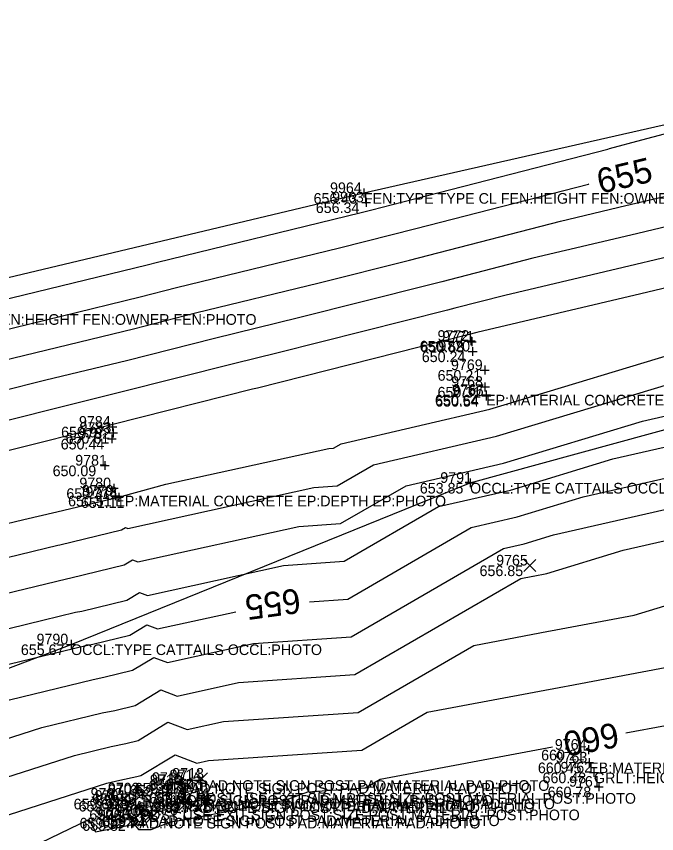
# Model space of a CAD drawing. Extents: x 2129350 to 2137777, y 657588 to 659885.
# Drawn here: x 2134017.7 to 2134089.9, y 659044.8 to 659137 of the extents above; entities that cross this region are included whole.
import ezdxf

# ---------------------------------------------------------------- set-up
doc = ezdxf.new("R2010")
doc.units = 0
for name, color, linetype in [('DT_X_Contour_Major', 7, 'Continuous'), ('DT_X_Contour_Minor', 7, 'Continuous'), ('DT_X_TIN_Hull', 7, 'Continuous'), ('RD_X_Cells', 7, 'Continuous'), ('SV_X_Occupation_Line', 7, 'Continuous'), ('SV_X_Random_Point', 7, 'Continuous'), ('SV_X_Shot_Marker', 7, 'Continuous'), ('SV_X_Text_Comment', 7, 'Continuous'), ('SV_X_Text_Elevation', 7, 'Continuous'), ('SV_X_Text_Name', 7, 'Continuous')]:
    doc.layers.add(name, color=color, linetype=linetype)

msp = doc.modelspace()

# ---------------------------------------------------------------- linework, layer by layer
at = {"layer": 'DT_X_Contour_Major'}
for points in [[(2133984.763, 659096.562), (2133998.002, 659097.665), (2134001.64, 659097.968), (2134007.291, 659099.346), (2134013.833, 659100.986), (2134031.695, 659105.339), (2134035.772, 659106.371), (2134054.144, 659110.846), (2134059.912, 659112.305), (2134062.733, 659113.033), (2134082.191, 659118.049), (2134082.236, 659118.06)], [(2134050.751, 659070.954), (2134055.065, 659071.25), (2134068.969, 659079.308), (2134074.177, 659080.515), (2134081.606, 659082.765), (2134111.977, 659089.686), (2134119.808, 659092.155), (2134130.097, 659094.792), (2134146.022, 659099.168)], [(2134086.41, 659056.154), (2134099.797, 659058.669), (2134106.214, 659059.949), (2134110.948, 659060.932), (2134128.703, 659064.536), (2134130.835, 659065.039), (2134151.277, 659070.077), (2134152.823, 659070.441), (2134154.17, 659070.79), (2134176.696, 659076.829), (2134178.859, 659076.97), (2134180.373, 659077.349), (2134180.728, 659077.11), (2134183.835, 659077.795)], [(2133949.597, 659046.76), (2133964.098, 659048.355), (2133973.018, 659050.173), (2133975.83, 659047.42), (2133976.393, 659049.146), (2133976.617, 659049.192), (2133986.103, 659056.365), (2133987.605, 659056.69), (2133997.253, 659058.741), (2133998.731, 659059.107), (2134000.25, 659059.52), (2134001.796, 659059.974), (2134002.899, 659059.699), (2134013.292, 659063.037), (2134025.401, 659065.979), (2134026.335, 659066.172), (2134030.508, 659067.186), (2134032.419, 659068.346), (2134033.637, 659067.879), (2134042.451, 659069.822)], [(2133982.762, 659033.609), (2133982.831, 659033.821), (2133983.338, 659033.924), (2133984.503, 659034.806), (2133984.688, 659034.846), (2134007.46, 659039.688), (2134007.609, 659039.725), (2134007.762, 659039.766), (2134007.917, 659039.812), (2134008.028, 659039.784), (2134020.538, 659043.802), (2134025.906, 659046.408), (2134026.667, 659044.999), (2134031.019, 659045.857), (2134031.487, 659045.273), (2134032.919, 659045.275), (2134035.135, 659046.152), (2134036.568, 659046.362), (2134048.024, 659048.581), (2134050.58, 659049.52), (2134057.054, 659049.964), (2134058.731, 659050.936), (2134078.155, 659054.6)]]:
    msp.add_lwpolyline(points, dxfattribs=at)
at = {"layer": 'DT_X_Contour_Minor'}
for points in [[(2133976.674, 659092.847), (2133977.522, 659091.483), (2133980.569, 659092.251), (2133984.24, 659093.177), (2133999.557, 659094.453), (2134002.293, 659094.681), (2134006.542, 659095.717), (2134017.451, 659098.452), (2134030.921, 659101.735), (2134037.914, 659103.505), (2134051.837, 659106.896), (2134062.046, 659109.479), (2134064.2, 659110.034), (2134079.051, 659113.863), (2134086.408, 659115.608), (2134096.359, 659117.968), (2134110.672, 659121.688), (2134113.284, 659122.316), (2134123.738, 659124.847), (2134133.178, 659127.116), (2134143.637, 659129.649), (2134152.762, 659131.842), (2134168.026, 659135.54)], [(2134167.919, 659131.932), (2134158.207, 659129.579), (2134143.576, 659126.064), (2134136.854, 659124.435), (2134122.145, 659120.901), (2134115.361, 659119.258), (2134111.231, 659118.265), (2134101.918, 659115.845), (2134086.965, 659112.298), (2134075.91, 659109.676), (2134065.666, 659107.035), (2134064.18, 659106.652), (2134049.53, 659102.946), (2134040.056, 659100.638), (2134030.148, 659098.13), (2134021.07, 659095.918), (2134005.794, 659092.088), (2134002.946, 659091.394), (2134001.112, 659091.241), (2133990.847, 659090.386), (2133980.378, 659087.745), (2133978.347, 659087.233), (2133975.261, 659092.198)], [(2133993.65, 659100.644), (2133996.447, 659100.877), (2134000.987, 659101.255), (2134008.04, 659102.975), (2134010.215, 659103.52), (2134032.469, 659108.943), (2134033.63, 659109.237), (2134056.451, 659114.796), (2134057.778, 659115.132), (2134061.267, 659116.032), (2134084.359, 659121.985), (2134084.561, 659122.058), (2134088.214, 659123.011), (2134109.184, 659128.595), (2134118.743, 659130.987)], [(2134163.653, 659127.317), (2134143.515, 659122.478), (2134140.529, 659121.755), (2134120.552, 659116.954), (2134117.438, 659116.2), (2134111.791, 659114.843), (2134107.476, 659113.722), (2134087.522, 659108.989), (2134072.77, 659105.489), (2134067.132, 659104.036), (2134066.314, 659103.825), (2134047.223, 659098.996), (2134042.198, 659097.772), (2134029.374, 659094.526), (2134024.688, 659093.384), (2134005.045, 659088.459), (2134003.599, 659088.107), (2134002.668, 659088.029), (2133997.455, 659087.595), (2133980.186, 659083.24), (2133979.173, 659082.984), (2133973.849, 659091.549)], [(2134095.816, 659107.514), (2134088.079, 659105.679), (2134069.63, 659101.303), (2134068.598, 659101.037), (2134068.448, 659100.998), (2134044.916, 659095.046), (2134044.34, 659094.906), (2134028.6, 659090.922), (2134028.306, 659090.85), (2134004.296, 659084.83), (2134004.251, 659084.82), (2134004.223, 659084.817), (2134004.063, 659084.804), (2133982.451, 659079.354), (2133980.16, 659078.782), (2133979.923, 659078.72), (2133973.446, 659077.098), (2133973.417, 659077.074), (2133973.133, 659079.326), (2133972.456, 659091.406)], [(2133999.642, 659075.668), (2134018.561, 659080.227), (2134022.304, 659081.087), (2134029.227, 659082.753), (2134031.57, 659083.394), (2134034.59, 659084.198), (2134052.934, 659088.241), (2134053.474, 659088.278), (2134054.316, 659088.767), (2134071.063, 659092.646), (2134094.947, 659099.882)], [(2134002.314, 659072.449), (2134022.394, 659077.328), (2134022.616, 659077.373), (2134029.566, 659079.062), (2134030.017, 659079.336), (2134030.304, 659079.226), (2134051.239, 659083.841), (2134053.872, 659084.021), (2134057.98, 659086.402), (2134071.841, 659089.613), (2134091.612, 659095.603)], [(2134005.973, 659069.312), (2134023.397, 659073.545), (2134023.855, 659073.64), (2134029.88, 659075.103), (2134030.817, 659075.672), (2134031.415, 659075.443), (2134049.545, 659079.44), (2134054.269, 659079.764), (2134061.643, 659084.037), (2134072.62, 659086.58), (2134088.277, 659091.324), (2134103.511, 659094.795)], [(2134009.632, 659066.175), (2134024.399, 659069.762), (2134025.095, 659069.906), (2134030.194, 659071.144), (2134031.618, 659072.009), (2134032.526, 659071.661), (2134047.85, 659075.039), (2134054.667, 659075.507), (2134065.306, 659081.673), (2134073.399, 659083.547), (2134084.941, 659087.045), (2134107.744, 659092.241)], [(2133985.855, 659043.583), (2134003.377, 659047.309), (2134004.058, 659047.477), (2134004.757, 659047.668), (2134005.469, 659047.877), (2134005.976, 659047.75), (2134024.269, 659053.625), (2134028.407, 659054.63), (2134030.054, 659054.97), (2134031.451, 659055.309), (2134034.821, 659057.356), (2134036.97, 659056.532), (2134041.073, 659057.437), (2134056.258, 659058.478), (2134069.282, 659066.027), (2134077.71, 659067.617), (2134077.927, 659067.658), (2134087.349, 659069.428), (2134121.013, 659079.703), (2134124.053, 659080.211), (2134127.308, 659081.14), (2134164.102, 659088.042)], [(2133963.234, 659044.551), (2133974.897, 659046.928), (2133977.216, 659044.658), (2133977.681, 659046.081), (2133977.961, 659046.138), (2133985.783, 659052.053), (2133987.022, 659052.321), (2133999.295, 659054.931), (2134000.507, 659055.23), (2134001.752, 659055.57), (2134003.02, 659055.942), (2134003.924, 659055.716), (2134016.951, 659059.9), (2134026.403, 659062.196), (2134027.575, 659062.438), (2134030.823, 659063.227), (2134033.22, 659064.682), (2134034.748, 659064.097), (2134044.461, 659066.238), (2134055.463, 659066.993), (2134072.632, 659076.944), (2134074.956, 659077.482), (2134078.271, 659078.486), (2134116.21, 659087.131)], [(2133979.305, 659043.085), (2133985.463, 659047.741), (2133986.439, 659047.952), (2134001.336, 659051.12), (2134002.282, 659051.354), (2134003.255, 659051.619), (2134004.244, 659051.909), (2134004.95, 659051.733), (2134020.61, 659056.762), (2134027.405, 659058.413), (2134028.814, 659058.704), (2134031.137, 659059.268), (2134034.021, 659061.019), (2134035.859, 659060.314), (2134042.767, 659061.837), (2134055.861, 659062.736), (2134074.558, 659073.572), (2134075.929, 659073.831), (2134075.965, 659073.838), (2134077.498, 659074.126), (2134086.096, 659076.75), (2134120.442, 659084.577)], [(2134007.002, 659043.767), (2134027.928, 659050.488), (2134029.41, 659050.848), (2134031.294, 659051.236), (2134031.765, 659051.351), (2134035.622, 659053.692), (2134038.081, 659052.75), (2134039.378, 659053.036), (2134056.656, 659054.221), (2134064.007, 659058.482), (2134079.49, 659061.402), (2134079.89, 659061.478), (2134097.201, 659064.73), (2134113.485, 659069.7), (2134126.289, 659071.838), (2134139.998, 659075.753), (2134158.234, 659079.174), (2134175.353, 659083.764)]]:
    msp.add_lwpolyline(points, dxfattribs=at)
at = {"layer": 'DT_X_TIN_Hull'}
msp.add_lwpolyline([(2134356.026, 659185.946), (2134303.515, 659173.01), (2134259.229, 659162.306), (2134216.068, 659153.312), (2134168.251, 659141.961), (2134125.876, 659132.549), (2134109.045, 659128.864), (2134056.892, 659117.026), (2133999.593, 659103.374), (2133973.207, 659091.255), (2133972.954, 659091.387), (2133971.1, 659091.461), (2133969.763, 659091.144), (2133967.604, 659091.082), (2133965.702, 659091.19), (2133965.451, 659091.228), (2133933.981, 659084.789), (2133923.278, 659083.026), (2133873.948, 659069.271), (2133819.308, 659054.807), (2133767.477, 659040.462), (2133725.976, 659030.566)], dxfattribs=at)
at = {"layer": 'RD_X_Cells'}
for points in [[(2134036.906, 659048.32), (2134038.353, 659047.927), (2134039.416, 659048.984), (2134039.032, 659050.434), (2134037.585, 659050.827), (2134036.522, 659049.77), (2134036.906, 659048.32)], [(2134030.571, 659046.464), (2134032.018, 659046.071), (2134033.081, 659047.128), (2134032.697, 659048.578), (2134031.25, 659048.971), (2134030.187, 659047.914), (2134030.571, 659046.464)]]:
    msp.add_lwpolyline(points, dxfattribs=at)
at = {"layer": 'SV_X_Occupation_Line'}
msp.add_lwpolyline([(2133964.235, 659050.817), (2133988.958, 659052.851), (2134023.903, 659066.142), (2134068.855, 659084.352), (2134158.11, 659108.791), (2134245.538, 659131.154), (2134308.77, 659149.808)], dxfattribs=at)
at = {"layer": 'SV_X_Random_Point'}
for p, q in [((2134074.918, 659074.372), (2134076.252, 659075.706)), ((2134074.918, 659075.706), (2134076.252, 659074.372)), ((2134037.929, 659050.333), (2134039.263, 659051.669)), ((2134037.929, 659051.669), (2134039.263, 659050.333)), ((2134035.49, 659049.61), (2134036.824, 659050.944)), ((2134035.49, 659050.944), (2134036.824, 659049.61)), ((2134031.26, 659048.666), (2134032.594, 659050.002)), ((2134031.26, 659050.002), (2134032.594, 659048.666)), ((2134029.303, 659048.071), (2134030.637, 659049.406)), ((2134029.303, 659049.406), (2134030.637, 659048.071)), ((2134036.06, 659047.411), (2134037.394, 659048.747)), ((2134036.06, 659048.747), (2134037.394, 659047.411)), ((2134038.491, 659047.792), (2134039.825, 659049.127)), ((2134038.491, 659049.127), (2134039.825, 659047.792)), ((2134030.147, 659045.654), (2134031.481, 659046.988)), ((2134030.147, 659046.988), (2134031.481, 659045.654)), ((2134032.36, 659046.02), (2134033.694, 659047.355)), ((2134032.36, 659047.355), (2134033.694, 659046.02))]:
    msp.add_line(p, q, dxfattribs=at)
at = {"layer": 'SV_X_Shot_Marker'}
for p, q in [((2134056.394, 659117.026), (2134057.394, 659117.026)), ((2134056.894, 659117.526), (2134056.894, 659116.526)), ((2134056.894, 659117.026), (2134056.894, 659117.026)), ((2134057.142, 659116.477), (2134057.142, 659115.477)), ((2134056.642, 659115.977), (2134057.642, 659115.977)), ((2134057.142, 659115.977), (2134057.142, 659115.977)), ((2134068.428, 659100.366), (2134069.428, 659100.366)), ((2134068.928, 659100.866), (2134068.928, 659099.866)), ((2134068.928, 659100.366), (2134068.928, 659100.366)), ((2134069.04, 659100.764), (2134069.04, 659099.764)), ((2134068.54, 659100.264), (2134069.54, 659100.264)), ((2134069.04, 659100.264), (2134069.04, 659100.264)), ((2134069.14, 659099.669), (2134069.14, 659098.669)), ((2134068.64, 659099.169), (2134069.64, 659099.169)), ((2134069.14, 659099.169), (2134069.14, 659099.169)), ((2134070, 659097.069), (2134071, 659097.069)), ((2134070.5, 659097.569), (2134070.5, 659096.569)), ((2134070.5, 659097.069), (2134070.5, 659097.069)), ((2134070.032, 659095.173), (2134071.032, 659095.173)), ((2134070.532, 659095.673), (2134070.532, 659094.673)), ((2134070.532, 659095.173), (2134070.532, 659095.173)), ((2134070.159, 659094.281), (2134071.159, 659094.281)), ((2134070.178, 659094.15), (2134071.178, 659094.15)), ((2134070.659, 659094.781), (2134070.659, 659093.781)), ((2134070.659, 659094.281), (2134070.659, 659094.281)), ((2134070.678, 659094.65), (2134070.678, 659093.65)), ((2134070.678, 659094.15), (2134070.678, 659094.15)), ((2134028.55, 659091.181), (2134028.55, 659090.181)), ((2134028.05, 659090.681), (2134029.05, 659090.681)), ((2134028.55, 659090.681), (2134028.55, 659090.681)), ((2134028.63, 659090.485), (2134028.63, 659089.485)), ((2134027.988, 659089.322), (2134028.988, 659089.322)), ((2134028.13, 659089.985), (2134029.13, 659089.985)), ((2134028.488, 659089.822), (2134028.488, 659088.822)), ((2134028.488, 659089.322), (2134028.488, 659089.322)), ((2134028.63, 659089.985), (2134028.63, 659089.985)), ((2134027.702, 659086.806), (2134027.702, 659085.806)), ((2134027.202, 659086.306), (2134028.202, 659086.306)), ((2134027.702, 659086.306), (2134027.702, 659086.306)), ((2134068.855, 659084.852), (2134068.855, 659083.852)), ((2134028.71, 659084.242), (2134028.71, 659083.242)), ((2134068.355, 659084.352), (2134069.355, 659084.352)), ((2134068.855, 659084.352), (2134068.855, 659084.352)), ((2134028.21, 659083.742), (2134029.21, 659083.742)), ((2134028.383, 659082.906), (2134029.383, 659082.906)), ((2134028.71, 659083.742), (2134028.71, 659083.742)), ((2134028.883, 659083.406), (2134028.883, 659082.406)), ((2134028.883, 659082.906), (2134028.883, 659082.906)), ((2134029.276, 659083.232), (2134029.276, 659082.232)), ((2134028.776, 659082.732), (2134029.776, 659082.732)), ((2134029.276, 659082.732), (2134029.276, 659082.732)), ((2134023.903, 659066.642), (2134023.903, 659065.642)), ((2134023.403, 659066.142), (2134024.403, 659066.142)), ((2134023.903, 659066.142), (2134023.903, 659066.142)), ((2134082.183, 659054.763), (2134082.183, 659053.763)), ((2134081.683, 659054.263), (2134082.683, 659054.263)), ((2134082.183, 659054.263), (2134082.183, 659054.263)), ((2134081.779, 659052.821), (2134082.779, 659052.821)), ((2134082.279, 659053.321), (2134082.279, 659052.321)), ((2134082.279, 659052.821), (2134082.279, 659052.821)), ((2134082.316, 659051.693), (2134083.316, 659051.693)), ((2134082.816, 659052.193), (2134082.816, 659051.193)), ((2134082.816, 659051.693), (2134082.816, 659051.693)), ((2134036.317, 659051.022), (2134036.317, 659050.022)), ((2134037.786, 659050.831), (2134038.786, 659050.831)), ((2134038.286, 659051.331), (2134038.286, 659050.331)), ((2134038.286, 659050.831), (2134038.286, 659050.831)), ((2134083.362, 659050.598), (2134083.362, 659049.598)), ((2134035.817, 659050.522), (2134036.817, 659050.522)), ((2134036.317, 659050.522), (2134036.317, 659050.522)), ((2134082.862, 659050.098), (2134083.862, 659050.098)), ((2134083.362, 659050.098), (2134083.362, 659050.098)), ((2134030.001, 659049.003), (2134030.001, 659048.003)), ((2134031.428, 659049.147), (2134032.428, 659049.147)), ((2134031.928, 659049.647), (2134031.928, 659048.647)), ((2134031.928, 659049.147), (2134031.928, 659049.147)), ((2134036.619, 659048.838), (2134036.619, 659047.838)), ((2134038.413, 659048.764), (2134039.413, 659048.764)), ((2134038.913, 659049.264), (2134038.913, 659048.264)), ((2134038.913, 659048.764), (2134038.913, 659048.764)), ((2134029.501, 659048.503), (2134030.501, 659048.503)), ((2134030.001, 659048.503), (2134030.001, 659048.503)), ((2134036.119, 659048.338), (2134037.119, 659048.338)), ((2134036.619, 659048.338), (2134036.619, 659048.338)), ((2134030.523, 659047.088), (2134030.523, 659046.088)), ((2134032.687, 659047.356), (2134032.687, 659046.356)), ((2134030.023, 659046.588), (2134031.023, 659046.588)), ((2134030.523, 659046.588), (2134030.523, 659046.588)), ((2134032.187, 659046.856), (2134033.187, 659046.856)), ((2134032.687, 659046.856), (2134032.687, 659046.856))]:
    msp.add_line(p, q, dxfattribs=at)

# ---------------------------------------------------------------- texts
at = {"layer": 'DT_X_Contour_Major'}
for s, rotation, p in [('655', 13.34362, (2134083.525, 659116.927)), ('655', 187.76647, (2134049.55, 659072.487)), ('660', 190.65926, (2134085.316, 659057.374))]:
    msp.add_text(s, height=2.8, rotation=rotation, dxfattribs=at).set_placement(p)
at = {"layer": 'SV_X_Text_Comment'}
for s, p in [('FEN:TYPE TYPE CL FEN:HEIGHT FEN:OWNER FEN:PHOTO', (2134056.894, 659115.826)), ('FEN:TYPE TYPE CL FEN:HEIGHT FEN:OWNER FEN:PHOTO', (2133999.595, 659102.174)), ('EP:MATERIAL CONCRETE EP:DEPTH EP:PHOTO', (2134070.659, 659093.081)), ('OCCL:TYPE CATTAILS OCCL:PHOTO', (2134068.855, 659083.152)), ('EP:MATERIAL CONCRETE EP:DEPTH EP:PHOTO', (2134028.883, 659081.706)), ('OCCL:TYPE CATTAILS OCCL:PHOTO', (2134023.903, 659064.942)), ('EB:MATERIAL ASPHALT EB:DEPTH EB:PHOTO', (2134082.279, 659051.621)), ('GRLT:HEIGHT 2.5 GRLT:PHOTO', (2134082.816, 659050.493)), ('PAD:NOTE SIGN POST PAD:MATERIAL PAD:PHOTO', (2134038.286, 659049.631)), ('PAD:NOTE SIGN POST PAD:MATERIAL PAD:PHOTO', (2134036.317, 659049.322)), ('PAD:NOTE SIGN POST PAD:MATERIAL PAD:PHOTO', (2134031.928, 659047.947)), ('POST:USE EXIT SIGN POST:SIZE POST:MATERIAL POST:PHOTO', (2134037.969, 659048.177)), ('PAD:NOTE SIGN POST PAD:MATERIAL PAD:PHOTO', (2134038.913, 659047.564)), ('PAD:NOTE SIGN POST PAD:MATERIAL PAD:PHOTO', (2134030.001, 659047.303)), ('PAD:NOTE SIGN POST PAD:MATERIAL PAD:PHOTO', (2134036.619, 659047.138)), ('POST:USE EXIT SIGN POST:SIZE POST:MATERIAL POST:PHOTO', (2134031.634, 659046.321)), ('PAD:NOTE SIGN POST PAD:MATERIAL PAD:PHOTO', (2134030.523, 659045.388)), ('PAD:NOTE SIGN POST PAD:MATERIAL PAD:PHOTO', (2134032.687, 659045.656))]:
    msp.add_text(s, height=1.2, dxfattribs=at).set_placement(p)
at = {"layer": 'SV_X_Text_Elevation'}
for s, p in [('656.43', (2134051.225, 659115.826)), ('656.34', (2134051.473, 659114.777)), ('650.82', (2134063.183, 659099.166)), ('650.58', (2134063.277, 659099.064)), ('650.24', (2134063.414, 659097.969)), ('650.21', (2134065.199, 659095.869)), ('650.31', (2134065.193, 659093.973)), ('650.64', (2134064.896, 659093.081)), ('650.54', (2134064.933, 659092.95)), ('650.97', (2134022.777, 659089.481)), ('650.44', (2134022.734, 659088.122)), ('650.61', (2134023.291, 659088.785)), ('650.09', (2134021.825, 659085.106)), ('650.31', (2134023.371, 659082.542)), ('653.85', (2134063.196, 659083.152)), ('650.51', (2134023.563, 659081.706)), ('651.11', (2134025.015, 659081.532)), ('656.85', (2134069.926, 659073.839)), ('655.67', (2134018.244, 659064.942)), ('660.21', (2134076.863, 659053.063)), ('660.45', (2134076.497, 659051.621)), ('660.48', (2134077.024, 659050.493)), ('659.87', (2134032.627, 659049.631)), ('659.50', (2134032.833, 659049.801)), ('659.48', (2134030.479, 659049.077)), ('659.91', (2134031.072, 659049.322)), ('660.78', (2134077.599, 659048.898)), ('659.60', (2134024.188, 659047.539)), ('659.55', (2134026.268, 659048.134)), ('659.91', (2134026.683, 659047.947)), ('659.91', (2134032.724, 659048.177)), ('659.91', (2134033.668, 659047.564)), ('659.91', (2134024.756, 659047.303)), ('659.76', (2134031.011, 659046.879)), ('659.91', (2134031.374, 659047.138)), ('659.75', (2134033.517, 659047.26)), ('659.93', (2134025.956, 659046.321)), ('659.92', (2134024.854, 659045.388)), ('659.82', (2134025.164, 659045.121)), ('659.74', (2134027.396, 659045.488)), ('659.91', (2134027.442, 659045.656))]:
    msp.add_text(s, height=1.2, dxfattribs=at).set_placement(p)
at = {"layer": 'SV_X_Text_Name'}
for s, p in [('9964', (2134053.077, 659117.026)), ('9963', (2134053.316, 659115.977)), ('9772', (2134065.186, 659100.366)), ('9771', (2134065.723, 659100.264)), ('9770', (2134065.285, 659099.169)), ('9769', (2134066.702, 659097.069)), ('9768', (2134066.734, 659095.173)), ('9766', (2134066.814, 659094.15)), ('9767', (2134066.87, 659094.281)), ('9784', (2134024.79, 659090.681)), ('9783', (2134024.86, 659089.985)), ('9782', (2134024.728, 659089.322)), ('9781', (2134024.366, 659086.306)), ('9780', (2134024.836, 659083.742)), ('9791', (2134065.5, 659084.352)), ('9779', (2134025.123, 659082.906)), ('9778', (2134025.516, 659082.732)), ('9765', (2134071.796, 659075.039)), ('9790', (2134020.01, 659066.142)), ('9764', (2134078.404, 659054.263)), ('9763', (2134078.49, 659052.821)), ('9762', (2134079.037, 659051.693)), ('9715', (2134033.02, 659050.522)), ('9714', (2134034.999, 659050.831)), ('9713', (2134035.299, 659051.001)), ('9716', (2134032.785, 659050.277)), ('9710', (2134034.568, 659049.377)), ('9761', (2134080.007, 659050.098)), ('9702', (2134026.096, 659048.739)), ('9701', (2134026.552, 659048.503)), ('9703', (2134028.044, 659049.334)), ('9704', (2134028.054, 659049.147)), ('9712', (2134035.871, 659048.46)), ('9711', (2134036.05, 659048.764)), ('9709', (2134027.741, 659047.521)), ('9717', (2134033.322, 659048.338)), ('9718', (2134033.421, 659048.079)), ('9705', (2134028.804, 659046.856)), ('9706', (2134029.068, 659046.688)), ('9707', (2134026.64, 659046.588)), ('9708', (2134026.921, 659046.321))]:
    msp.add_text(s, height=1.2, dxfattribs=at).set_placement(p)

doc.saveas('drawing.dxf')
